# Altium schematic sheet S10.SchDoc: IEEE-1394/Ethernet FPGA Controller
size 381 x 254 mm; Revision: 3.2; SheetNumber: 10; SheetTotal: 10
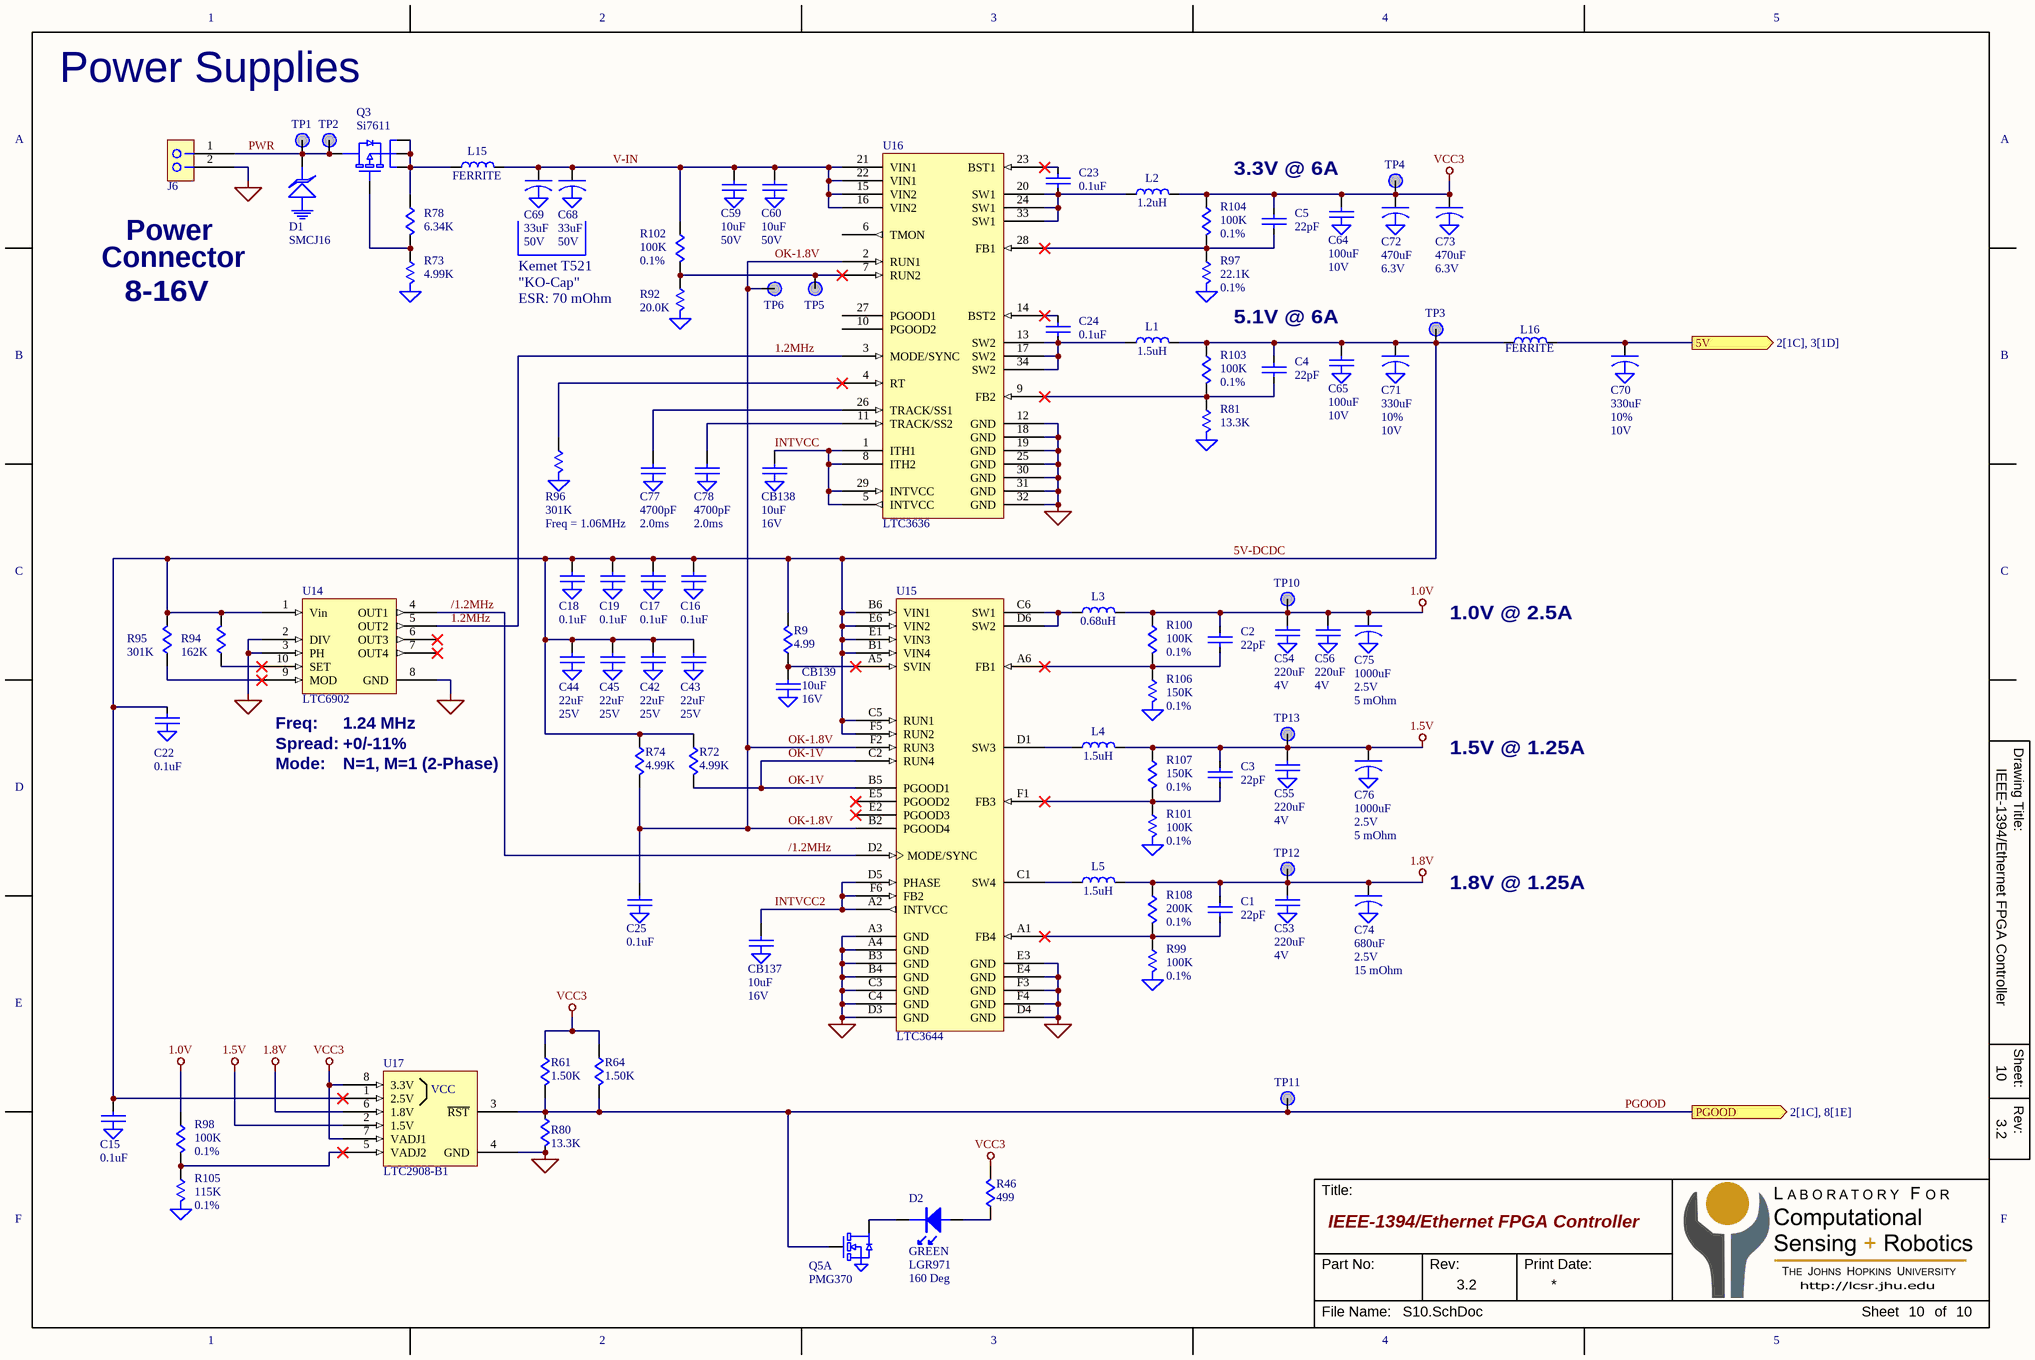
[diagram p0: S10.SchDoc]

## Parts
C1  22pF  [C0402]
C2  22pF  [C0402]
C3  22pF  [C0402]
C4  22pF  [C0402]
C5  22pF  [C0402]
C15  0.1uF  [C0402]
C16  0.1uF  [C0402]
C17  0.1uF  [C0402]
C18  0.1uF  [C0402]
C19  0.1uF  [C0402]
C22  0.1uF  [C0402]
C23  0.1uF  [C0402]
C24  0.1uF  [C0402]
C25  0.1uF  [C0402]
C42  22uF  [C0805]
C43  22uF  [C0805]
C44  22uF  [C0805]
C45  22uF  [C0805]
C53  220uF  [C1206]
C54  220uF  [C1206]
C55  220uF  [C1206]
C56  220uF  [C1206]
C59  10uF  [C1210]
C60  10uF  [C1210]
C64  100uF  [C1210]
C65  100uF  [C1210]
C68  33uF  Voltage: 50V  [CAP-D-31]
C69  33uF  Voltage: 50V  [CAP-D-31]
C70  330uF  Voltage: 10V  Tol: 10%  [CAP-D-31]
C71  330uF  Voltage: 10V  Tol: 10%  [CAP-D-31]
C72  470uF  Volts: 6.3V  [CAP-D-31]
C73  470uF  Volts: 6.3V  [CAP-D-31]
C74  680uF  Voltage: 2.5V  ESR: 15 mOhm  [CAP-D-43]
C75  1000uF  Voltage: 2.5V  ESR: 5 mOhm  [CAP-D-43]
C76  1000uF  Voltage: 2.5V  ESR: 5 mOhm  [CAP-D-43]
C77  4700pF  Parameter 1: 2.0ms  [C0402]
C78  4700pF  Parameter 1: 2.0ms  [C0402]
CB137  10uF  [CB0603]
CB138  10uF  [CB0603]
CB139  10uF  [CB0603]
D1  SMCJ16  [DIODE-SMC]
D2  Color: GREEN  P/N: LGR971  Angle: 160 Deg  [LED-0805]  (hidden comment: LED)
J6  HEADER 2  [HDR-2x1-100]  (value not drawn)
L1  1.5uH  [INDUCTOR-XGL5030]
L2  1.2uH  [INDUCTOR-XGL5030]
L3  0.68uH  [INDUCTOR-XAL4040]
L4  1.5uH  [INDUCTOR-XAL4040]
L5  1.5uH  [INDUCTOR-XAL4040]
L15  FERRITE  [R1206]
L16  FERRITE  [R1206]
Q3  Si7611  [PowerPak-1212]
Q5  PMG370  [SC70-6-NP]  (part A of 2)
R9  4.99  [R0402]
R46  499  [R0402]
R61  1.50K  [R0402]
R64  1.50K  [R0402]
R72  4.99K  [R0402]
R73  4.99K  [R0402]
R74  4.99K  [R0402]
R78  6.34K  [R0402]
R80  13.3K  [R0402]
R81  13.3K  [R0402]
R92  20.0K  [R0402]
R94  162K  [R0402]
R95  301K  [R0402]
R96  301K  Parameter 1: Freq = 1.06MHz  [R0402]
R97  22.1K  [R0402]
R98  100K  Parameter 1: 0.1%  [R0402]
R99  100K  [R0402]
R100  100K  Parameter 1: 0.1%  [R0402]
R101  100K  [R0402]
R102  100K  [R0402]
R103  100K  Parameter 1: 0.1%  [R0402]
R104  100K  Parameter 1: 0.1%  [R0402]
R105  115K  [R0402]
R106  150K  [R0402]
R107  150K  Parameter 1: 0.1%  [R0402]
R108  200K  [R0402]
TP1  PAD  [PAD25-SM]  (value not drawn)  (no BOM)
TP2  PAD  [PAD25-SM]  (value not drawn)  (no BOM)
TP3  PAD  [PAD25-SM]  (value not drawn)  (no BOM)
TP4  PAD  [PAD25-SM]  (value not drawn)  (no BOM)
TP5  PAD  [PAD25-SM]  (value not drawn)  (no BOM)
TP6  PAD  [PAD25-SM]  (value not drawn)  (no BOM)
TP10  PAD  [PAD25-SM]  (value not drawn)  (no BOM)
TP11  PAD  [PAD25-SM]  (value not drawn)  (no BOM)
TP12  PAD  [PAD25-SM]  (value not drawn)  (no BOM)
TP13  PAD  [PAD25-SM]  (value not drawn)  (no BOM)
U14  LTC6902  [MSOP-10]
U15  LTC3644  [BGA-36-08mm]
U16  LTC3636  [QFN-28-LTC3636]
U17  LTC2908-B1  [SOT-23-8]

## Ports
5V (out, see 2[1C], 3[1D]), PGOOD (out, see 2[1C], 8[1E])

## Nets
1.0V: C2.1 C54.1 C56.1 C75.1 L3.2 R98.1 R100.1 TP10.1
1.5V: C3.1 C55.1 C76.1 L4.2 R107.1 TP13.1 U17.2(1.5V)
1.8V: C1.1 C53.1 C74.1 L5.2 R108.1 TP12.1 U17.6(1.8V)
GND: C15.2(GND) C16.2(GND) C17.2(GND) C18.2(GND) C19.2(GND) C22.2(GND) C25.2(GND) C42.2(GND) C43.2(GND) C44.2(GND) C45.2(GND) C53.2(GND) C54.2(GND) C55.2(GND) C56.2(GND) C59.2(GND) C60.2(GND) C64.2(GND) C65.2(GND) C68.2(GND) C69.2(GND) C70.2(GND) C71.2(GND) C72.2(GND) C73.2(GND) C74.2(GND) C75.2(GND) C76.2(GND) C77.2(GND) C78.2(GND) CB137.2(GND) CB138.2(GND) CB139.2(GND) D1.2(GND) J6.2 Q5.1(S1) R73.2(GND) R80.2 R81.2(GND) R92.2(GND) R96.2(GND) R97.2(GND) R99.2(GND) R101.2(GND) R105.2(GND) R106.2(GND) U14.2(DIV) U14.3(PH) U14.8(GND) U15.A3(GND) U15.A4(GND) U15.B3(GND) U15.B4(GND) U15.C3(GND) U15.C4(GND) U15.D3(GND) U15.D4(GND) U15.E3(GND) U15.E4(GND) U15.F3(GND) U15.F4(GND) U16.12(GND) U16.18(GND) U16.19(GND) U16.25(GND) U16.30(GND) U16.31(GND) U16.32(GND) U17.4(GND)
VCC3: C5.1 C64.1 C72.1 C73.1 L2.2 R46.2 R61.1 R64.1 R104.1 TP4.1 U17.7(VADJ1) U17.8(3.3V)
1.2MHz: U14.5(OUT2) U16.3(MODE/SYNC)
5V: C70.1 L16.2 ; port 5V
5V-DCDC: C4.1 C15.1 C16.1 C17.1 C18.1 C19.1 C22.1 C42.1 C43.1 C44.1 C45.1 C65.1 C71.1 L1.2 L16.1 R9.2 R72.1 R74.1 R94.2 R95.2 R103.1 TP3.1 U14.1(Vin) U15.B1(VIN4) U15.B6(VIN1) U15.C5(RUN1) U15.E1(VIN3) U15.E6(VIN2) U15.F5(RUN2) U17.1(2.5V)
/1.2MHz: U14.4(OUT1) U15.D2(MODE/SYNC)
INTVCC: CB138.1 U16.1(ITH1) U16.5(INTVCC) U16.8(ITH2) U16.29(INTVCC)
INTVCC2: CB137.1 U15.A2(INTVCC) U15.D5(PHASE) U15.F6(FB2)
OK-1.8V: C25.1 R74.2 TP6.1 U15.B2(PGOOD4) U15.F2(RUN3) U16.2(RUN1)
OK-1V: R72.2 U15.B5(PGOOD1) U15.C2(RUN4)
PGOOD: Q5.2(G1) R61.2 R64.2 R80.1 TP11.1 U17.3(~{RST}) ; port PGOOD
PWR: D1.1 J6.1 Q3.5(D) TP1.1 TP2.1
V-IN: C59.1 C60.1 C68.1 C69.1 L15.2 R102.1 U16.15(VIN2) U16.16(VIN2) U16.21(VIN1) U16.22(VIN1)
NetC1_2: C1.2 R99.1 R108.2 U15.A1(FB4)
NetC2_2: C2.2 R100.2 R106.1 U15.A6(FB1)
NetC3_2: C3.2 R101.1 R107.2 U15.F1(FB3)
NetC4_2: C4.2 R81.1 R103.2 U16.9(FB2)
NetC5_2: C5.2 R97.1 R104.2 U16.28(FB1)
NetC23_1: C23.1 U16.23(BST1)
NetC23_2: C23.2 L2.1 U16.20(SW1) U16.24(SW1) U16.33(SW1)
NetC24_1: C24.1 U16.14(BST2)
NetC24_2: C24.2 L1.1 U16.13(SW2) U16.17(SW2) U16.34(SW2)
NetC77_1: C77.1 U16.26(TRACK/SS1)
NetC78_1: C78.1 U16.11(TRACK/SS2)
NetCB139_1: CB139.1 R9.1 U15.A5(SVIN)
NetD2_1: D2.1(C) Q5.6(D1)
NetD2_2: D2.2(A) R46.1
NetL3_1: L3.1 U15.C6(SW1) U15.D6(SW2)
NetL4_1: L4.1 U15.D1(SW3)
NetL5_1: L5.1 U15.C1(SW4)
NetL15_1: L15.1 Q3.1(S) Q3.2(S) Q3.3(S) R78.1
NetQ3_4: Q3.4(G) R73.1 R78.2
NetR92_1: R92.1 R102.2 TP5.1 U16.7(RUN2)
NetR94_1: R94.1 U14.10(SET)
NetR95_1: R95.1 U14.9(MOD)
NetR96_1: R96.1 U16.4(RT)
NetR98_2: R98.2 R105.1 U17.5(VADJ2)

Not connected (* = marked no-connect by the designer): U14 6(OUT3)* 7(OUT4)*; U15 E2(PGOOD3)* E5(PGOOD2)*; U16 6(TMON) 10(PGOOD2) 27(PGOOD1)

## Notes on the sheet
- Power Supplies
- 3.3V @ 6A
- 8-16V
- (near J6) Power
- Connector
- Kemet T521
- ESR: 70 mOhm
- "KO-Cap"
- 5.1V @ 6A
- 1.0V @ 2.5A
- (near U14) Freq:
- Spread:
- Mode:
- (near U14) 1.24 MHz
- +0/-11%
- N=1, M=1 (2-Phase)
- 1.5V @ 1.25A
- 1.8V @ 1.25A

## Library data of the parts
C1-C5 C23 C24 = CAP
C15-C19 C22 C25 C42-C45 C53-C56 C59 C60 C64 C65 C77 C78 CB137-CB139 = CAP-GND
C68 C69 = CAP-POL-GND: Type: Tant
C70 C71 = CAP-POL-GND: Type: SpeedPower
C72 C73 = CAP-POL-GND
C74-C76 = CAP-POL-GND: Part #: Kemet: T530X158M2R5ATE005
D1 = TVS-GND
L1-L5 L15 L16 = INDUCTOR
Q3 = MOSFET-P-PPACK
Q5 = MOSFET-N-DUAL6
R9 R46 R61 R64 R72 R74 R78 R80 R94 R95 R98 R100 R102-R104 R107 R108 = R
R73 R81 R92 R96 R97 R99 R101 R105 R106 = R-GND
U17 = LTC2908-B1-SOT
